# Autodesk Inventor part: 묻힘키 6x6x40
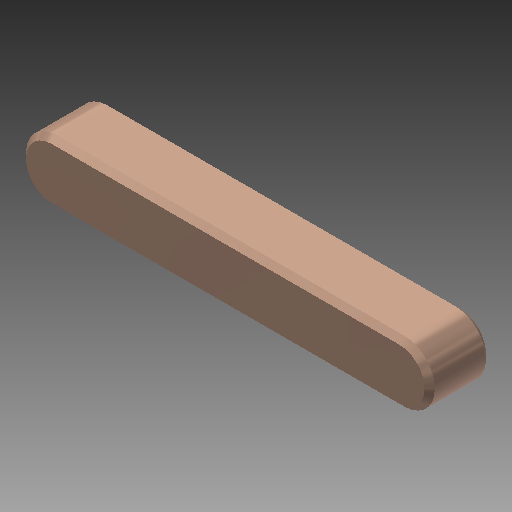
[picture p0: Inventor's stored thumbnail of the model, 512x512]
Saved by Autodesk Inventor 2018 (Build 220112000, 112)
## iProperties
Created: 2013-07
Part Number: 묻힘키 6x6x40
Document SubType Name: Modeling
Designer: SeoGD™[esajin.kr]
Density: 1 g/cm^3
Mass: 1.24965 g
Surface Area: 8.89646 cm^2
Volume: 1.24965 cm^3
Material: 강철, 연강
Appearance: 강철(1)
Author: SeoGD™[esajin.kr]
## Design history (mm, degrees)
sketch "스케치1"
  geometry: L1 (15, 3)-(-19, 3) reference; L2 (-19, -3)-(15, -3) reference; A1 r 3 centre (15, 0) between (15, -3) and (15, 3) reference; A2 r 3 centre (-19, 0) between (-19, 3) and (-19, -3) reference
extrude "돌출1" new body sketch "스케치1" distance "d0" = 6; taper "d1" = 0 deg
chamfer "모따기1" distance "d2" = 0.5; stored, may be unused: second distance "d3" = 2, angle "d4" = 45 deg
node "솔리드1"
node "참조5"
